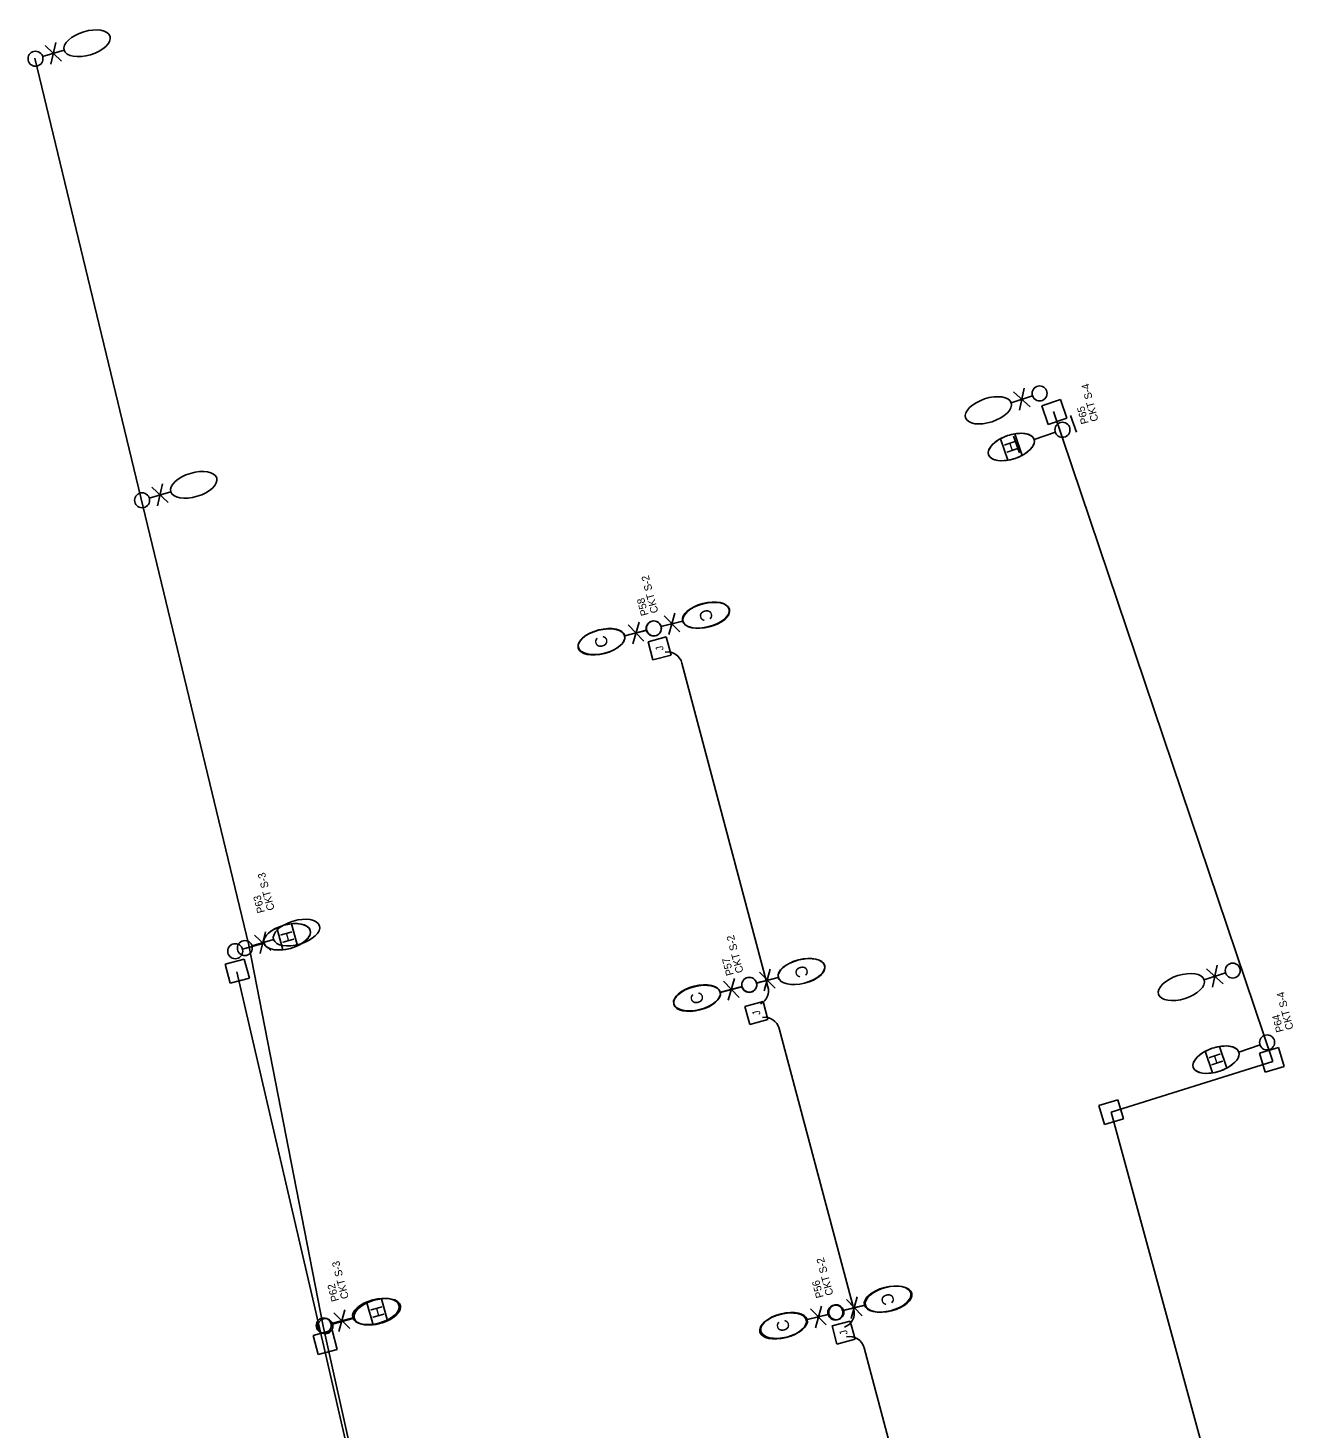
# Model space of a CAD drawing. Extents: x 925407 to 931638, y 609358 to 637063.
# Drawn here: x 930272.5 to 930690.6, y 629618 to 630080.5 of the extents above; entities that cross this region are included whole.
import ezdxf

# ---------------------------------------------------------------- set-up
doc = ezdxf.new("R2010")
doc.units = 0
for name, color, linetype in [('ActivePointCell_dp', 7, 'Continuous'), ('ConduitDB', 7, 'Continuous'), ('ConduitOT', 7, 'Continuous'), ('JunctBoxA', 7, 'Continuous'), ('LiteCond_ep', 7, 'Continuous'), ('Miscellaneous2', 7, 'Continuous'), ('PoleLight', 7, 'Continuous'), ('PoleLight_ep', 7, 'Continuous'), ('PullBox', 7, 'Continuous'), ('TextLabel', 7, 'Continuous')]:
    doc.layers.add(name, color=color, linetype=linetype)

msp = doc.modelspace()

# ---------------------------------------------------------------- linework, layer by layer
at = {"layer": 'ActivePointCell_dp'}
for p, q in [((930619.03, 629946.95), (930617.05, 629952.45)), ((930600.22, 629940.16), (930598.24, 629945.66))]:
    msp.add_line(p, q, dxfattribs=at)
at = {"layer": 'ConduitDB'}
msp.add_line((930683.97, 629739.06), (930630.48, 629722.29), dxfattribs=at)
at = {"layer": 'ConduitOT'}
for p, q in [((930683.97, 629739.06), (930611.45, 629953.81)), ((930517.08, 629763.75), (930488.66, 629870.66)), ((930370.28, 629644.9), (930341.57, 629768.65)), ((930545.46, 629657.25), (930520.74, 629749.96)), ((930630.48, 629722.29), (930687.25, 629514.41)), ((930397.38, 629526.67), (930370.31, 629644.91)), ((930571.71, 629558.43), (930548.86, 629644.47))]:
    msp.add_line(p, q, dxfattribs=at)
for centre, start, end in [((930483.83, 629869.38), 14.8905, 97.7384), ((930512.25, 629762.46), 298.3471, 14.8905), ((930515.91, 629748.68), 14.8905, 97.7384), ((930540.63, 629655.97), 289.9661, 14.8904), ((930544.03, 629643.19), 14.8905, 101.353)]:
    msp.add_arc(centre, 5, start, end, dxfattribs=at)
at = {"layer": 'LiteCond_ep'}
for p, q in [((930274.78, 630070.52), (930345.54, 629777.49)), ((930345.54, 629777.49), (930370.05, 629651.65)), ((930370.05, 629651.65), (930398.78, 629523.26))]:
    msp.add_line(p, q, dxfattribs=at)
at = {"layer": 'Miscellaneous2'}
for p, q in [((930593.95, 629944.82), (930593.95, 629944.82)), ((930593.95, 629944.82), (930596.35, 629937.7)), ((930601.09, 629939.29), (930598.69, 629946.42)), ((930598.69, 629946.42), (930598.69, 629946.42)), ((930354.77, 629783.21), (930356.78, 629775.97)), ((930361.6, 629777.31), (930359.59, 629784.55)), ((930361.6, 629777.31), (930361.6, 629777.31)), ((930356.78, 629775.97), (930356.78, 629775.97)), ((930661.6, 629742.42), (930661.6, 629742.42)), ((930661.6, 629742.42), (930664, 629735.3)), ((930668.74, 629736.89), (930666.34, 629744.02)), ((930666.34, 629744.02), (930666.34, 629744.02)), ((930384.55, 629659.34), (930386.56, 629652.09)), ((930391.38, 629653.43), (930389.37, 629660.67)), ((930391.38, 629653.43), (930391.38, 629653.43)), ((930386.56, 629652.09), (930386.56, 629652.09))]:
    msp.add_line(p, q, dxfattribs=at)
for centre, major_axis, start_param, end_param in [((930597.52, 629942.06), (7.51, 2.53), 1.249648, 1.891946), ((930597.52, 629942.06), (7.51, 2.53), 4.391271, 5.033538), ((930597.52, 629942.06), (7.51, 2.53), 4.391241, 4.391271), ((930358.18, 629780.26), (-7.63, -2.12), 4.391271, 5.033538), ((930358.18, 629780.26), (-7.63, -2.12), 4.391241, 4.391271), ((930358.18, 629780.26), (-7.63, -2.12), 1.249648, 1.891946), ((930665.17, 629739.66), (7.51, 2.53), 1.249648, 1.891946), ((930665.17, 629739.66), (7.51, 2.53), 4.391271, 5.033538), ((930665.17, 629739.66), (7.51, 2.53), 4.391241, 4.391271), ((930387.97, 629656.38), (-7.63, -2.12), 4.391271, 5.033538), ((930387.97, 629656.38), (-7.63, -2.12), 4.391241, 4.391271), ((930387.97, 629656.38), (-7.63, -2.12), 1.249648, 1.891946)]:
    msp.add_ellipse(centre, major_axis=major_axis, ratio=0.5, start_param=start_param, end_param=end_param, dxfattribs=at)
at = {"layer": 'PoleLight'}
for p, q in [((930596.35, 629937.7), (930593.95, 629944.82)), ((930598.69, 629946.42), (930601.09, 629939.29)), ((930612.06, 629946.96), (930605.02, 629944.58)), ((930481.69, 629882.73), (930488.88, 629884.58)), ((930476.9, 629881.49), (930469.71, 629879.64)), ((930356.78, 629775.97), (930354.77, 629783.21)), ((930359.59, 629784.55), (930361.6, 629777.31)), ((930343.4, 629776.16), (930350.55, 629778.14)), ((930508.5, 629763.75), (930501.3, 629761.9)), ((930513.29, 629764.99), (930520.48, 629766.84)), ((930664, 629735.3), (930661.6, 629742.42)), ((930666.34, 629744.02), (930668.74, 629736.89)), ((930679.71, 629744.56), (930672.67, 629742.19)), ((930386.56, 629652.09), (930384.55, 629659.34)), ((930389.37, 629660.67), (930391.38, 629653.43)), ((930541.75, 629656.75), (930548.94, 629658.6)), ((930373.18, 629652.28), (930380.33, 629654.27)), ((930536.95, 629655.52), (930529.76, 629653.67))]:
    msp.add_line(p, q, dxfattribs=at)
for centre in [(930614.41, 629947.75), (930614.41, 629947.75), (930479.3, 629882.11), (930341.01, 629775.5), (930341.01, 629775.5), (930510.89, 629764.37), (930682.05, 629745.35), (930682.05, 629745.35), (930539.35, 629656.13), (930370.79, 629651.62), (930370.79, 629651.62)]:
    msp.add_circle(centre, 2.48, dxfattribs=at)
for centre, major_axis in [((930597.52, 629942.06), (7.51, 2.53)), ((930496.55, 629886.55), (7.67, 1.97)), ((930462.04, 629877.67), (7.67, 1.97)), ((930358.18, 629780.26), (-7.63, -2.12)), ((930528.15, 629768.81), (7.67, 1.97)), ((930493.63, 629759.93), (7.67, 1.97)), ((930665.17, 629739.66), (7.51, 2.53)), ((930556.61, 629660.57), (7.67, 1.97)), ((930387.97, 629656.38), (-7.63, -2.12)), ((930522.09, 629651.69), (7.67, 1.97))]:
    msp.add_ellipse(centre, major_axis=major_axis, ratio=0.5, dxfattribs=at)
for centre, major_axis, start_param, end_param in [((930597.52, 629942.06), (7.51, 2.53), 1.891945, 4.391241), ((930597.52, 629942.06), (7.51, 2.53), 0.847605, 1.249648), ((930597.52, 629942.06), (7.51, 2.53), 5.033538, 6.283185), ((930597.52, 629942.06), (7.51, 2.53), 0, 0.847605), ((930358.18, 629780.26), (-7.63, -2.12), 5.033538, 6.283185), ((930358.18, 629780.26), (-7.63, -2.12), 1.891945, 4.391241), ((930358.18, 629780.26), (-7.63, -2.12), 0, 0.847605), ((930358.18, 629780.26), (-7.63, -2.12), 0.847605, 1.249648), ((930665.17, 629739.66), (7.51, 2.53), 1.891945, 4.391241), ((930665.17, 629739.66), (7.51, 2.53), 0.847605, 1.249648), ((930665.17, 629739.66), (7.51, 2.53), 5.033538, 6.283185), ((930665.17, 629739.66), (7.51, 2.53), 0, 0.847605), ((930387.97, 629656.38), (-7.63, -2.12), 5.033538, 6.283185), ((930387.97, 629656.38), (-7.63, -2.12), 1.891945, 4.391241), ((930387.97, 629656.38), (-7.63, -2.12), 0, 0.847605), ((930387.97, 629656.38), (-7.63, -2.12), 0.847605, 1.249648)]:
    msp.add_ellipse(centre, major_axis=major_axis, ratio=0.5, start_param=start_param, end_param=end_param, dxfattribs=at)
at = {"layer": 'PoleLight_ep'}
for p, q in [((930283.62, 630069.56), (930278.22, 630074.66)), ((930281.77, 630075.72), (930280.06, 630068.5)), ((930277.36, 630071.05), (930284.47, 630073.18)), ((930604.51, 629959), (930597.45, 629956.67)), ((930598.21, 629960.31), (930603.75, 629955.36)), ((930600.22, 629954.2), (930601.74, 629961.47)), ((930312.61, 629925.17), (930319.72, 629927.3)), ((930318.86, 629923.69), (930313.46, 629928.78)), ((930317.02, 629929.85), (930315.31, 629922.62)), ((930472.46, 629877.03), (930474.49, 629884.17)), ((930481.79, 629882.73), (930489, 629884.53)), ((930487.9, 629880.99), (930482.73, 629886.32)), ((930486.33, 629887.22), (930484.29, 629880.08)), ((930476.99, 629881.52), (930469.79, 629879.72)), ((930470.89, 629883.27), (930476.06, 629877.93)), ((930346.56, 629777.24), (930353.68, 629779.37)), ((930352.82, 629775.76), (930347.42, 629780.85)), ((930350.98, 629781.92), (930349.26, 629774.69)), ((930519.42, 629763.28), (930514.25, 629768.62)), ((930517.85, 629769.52), (930515.82, 629762.38)), ((930668.34, 629768.34), (930661.26, 629766.08)), ((930662.05, 629769.71), (930667.55, 629764.72)), ((930664.01, 629763.58), (930665.59, 629770.84)), ((930508.52, 629763.82), (930501.31, 629762.01)), ((930502.41, 629765.56), (930507.58, 629760.23)), ((930503.98, 629759.33), (930506.01, 629766.47)), ((930513.32, 629765.02), (930520.52, 629766.83)), ((930531.17, 629657.34), (930536.34, 629652.01)), ((930532.74, 629651.11), (930534.77, 629658.25)), ((930542.08, 629656.81), (930549.28, 629658.61)), ((930548.18, 629655.06), (930543.01, 629660.4)), ((930546.61, 629661.3), (930544.58, 629654.16)), ((930372.66, 629652.48), (930379.83, 629654.41)), ((930378.88, 629650.82), (930373.62, 629656.07)), ((930377.21, 629657.03), (930375.29, 629649.86)), ((930537.28, 629655.6), (930530.07, 629653.8))]:
    msp.add_line(p, q, dxfattribs=at)
for centre, radius in [((930274.99, 630070.34), 2.47), ((930606.86, 629959.77), 2.48), ((930310.24, 629924.46), 2.47), ((930479.39, 629882.13), 2.48), ((930344.19, 629776.53), 2.47), ((930670.69, 629769.1), 2.47), ((930510.92, 629764.42), 2.48), ((930539.68, 629656.2), 2.48), ((930370.27, 629651.84), 2.47)]:
    msp.add_circle(centre, radius, dxfattribs=at)
for centre, major_axis in [((930292.06, 630075.45), (7.59, 2.27)), ((930589.93, 629954.19), (-7.52, -2.48)), ((930327.31, 629929.57), (7.59, 2.27)), ((930496.68, 629886.46), (7.68, 1.93)), ((930462.11, 629877.79), (-7.68, -1.93)), ((930361.26, 629781.64), (7.59, 2.27)), ((930528.2, 629768.76), (7.68, 1.93)), ((930653.72, 629763.66), (-7.54, -2.42)), ((930493.63, 629760.09), (-7.68, -1.93)), ((930556.96, 629660.54), (7.68, 1.93)), ((930387.48, 629656.47), (7.65, 2.06)), ((930522.39, 629651.87), (-7.68, -1.93))]:
    msp.add_ellipse(centre, major_axis=major_axis, ratio=0.5, dxfattribs=at)
at = {"layer": 'PullBox'}
for p, q in [((930607.59, 629955.68), (930613.78, 629957.81)), ((930613.78, 629957.81), (930615.91, 629951.62)), ((930609.72, 629949.49), (930607.59, 629955.68)), ((930615.91, 629951.62), (930609.72, 629949.49)), ((930477.46, 629877.74), (930483.45, 629879.33)), ((930483.45, 629879.33), (930485.04, 629873.34)), ((930479.05, 629871.75), (930477.46, 629877.74)), ((930485.04, 629873.34), (930479.05, 629871.75)), ((930337.67, 629771.22), (930344, 629772.9)), ((930344, 629772.9), (930345.68, 629766.57)), ((930339.35, 629764.89), (930337.67, 629771.22)), ((930345.68, 629766.57), (930339.35, 629764.89)), ((930509.48, 629757.28), (930515.47, 629758.87)), ((930515.47, 629758.87), (930517.06, 629752.89)), ((930511.07, 629751.3), (930509.48, 629757.28)), ((930517.06, 629752.89), (930511.07, 629751.3)), ((930679.56, 629741.79), (930685.83, 629743.68)), ((930681.45, 629735.52), (930679.56, 629741.79)), ((930685.83, 629743.68), (930687.72, 629737.41)), ((930687.72, 629737.41), (930681.45, 629735.52)), ((930626.4, 629724.48), (930632.67, 629726.37)), ((930628.29, 629718.21), (930626.4, 629724.48)), ((930632.67, 629726.37), (930634.56, 629720.1)), ((930634.56, 629720.1), (930628.29, 629718.21)), ((930538.3, 629651.7), (930544.28, 629653.29)), ((930544.28, 629653.29), (930545.88, 629647.31)), ((930366.73, 629648.59), (930373.06, 629650.28)), ((930368.42, 629642.26), (930366.73, 629648.59)), ((930373.06, 629650.28), (930374.75, 629643.95)), ((930539.89, 629645.72), (930538.3, 629651.7)), ((930374.75, 629643.95), (930368.42, 629642.26)), ((930545.88, 629647.31), (930539.89, 629645.72))]:
    msp.add_line(p, q, dxfattribs=at)

# ---------------------------------------------------------------- texts
at = {"layer": 'ActivePointCell_dp'}
for s, p in [('CKT S-4', (930626.33, 629950.85)), ('P65', (930623.1, 629950)), ('CKT S-2', (930480.87, 629887.52)), ('P58', (930477.63, 629886.66)), ('CKT S-3', (930354.06, 629789.31)), ('P63', (930350.82, 629788.45)), ('CKT S-2', (930509.03, 629768.65)), ('P57', (930505.79, 629767.79)), ('CKT S-4', (930690.82, 629749.91)), ('P64', (930687.58, 629749.06)), ('CKT S-3', (930378.59, 629660.97)), ('CKT S-2', (930538.74, 629662.12)), ('P56', (930535.5, 629661.27)), ('P62', (930375.35, 629660.11))]:
    msp.add_text(s, height=2.5, rotation=104.7826, dxfattribs=at).set_placement(p)
at = {"layer": 'JunctBoxA'}
for p in [(930482.66, 629875.05), (930514.68, 629754.59), (930543.5, 629649.01)]:
    msp.add_text('J', height=2.48, rotation=104.8905, dxfattribs=at).set_placement(p)
at = {"layer": 'TextLabel'}
for s, rotation, p in [('H', 108.6193, (930600, 629940.96)), ('C', 284.4307, (930494.15, 629887.86)), ('C', 104.4307, (930464.44, 629876.35)), ('H', 285.5029, (930355.77, 629781.49)), ('C', 284.4307, (930525.75, 629770.13)), ('C', 104.4307, (930496.04, 629758.61)), ('H', 108.6193, (930667.65, 629738.56)), ('C', 284.4307, (930554.2, 629661.89)), ('H', 285.5029, (930385.55, 629657.61)), ('C', 104.4307, (930524.49, 629650.38))]:
    msp.add_text(s, height=4, rotation=rotation, dxfattribs=at).set_placement(p)

doc.saveas('drawing.dxf')
